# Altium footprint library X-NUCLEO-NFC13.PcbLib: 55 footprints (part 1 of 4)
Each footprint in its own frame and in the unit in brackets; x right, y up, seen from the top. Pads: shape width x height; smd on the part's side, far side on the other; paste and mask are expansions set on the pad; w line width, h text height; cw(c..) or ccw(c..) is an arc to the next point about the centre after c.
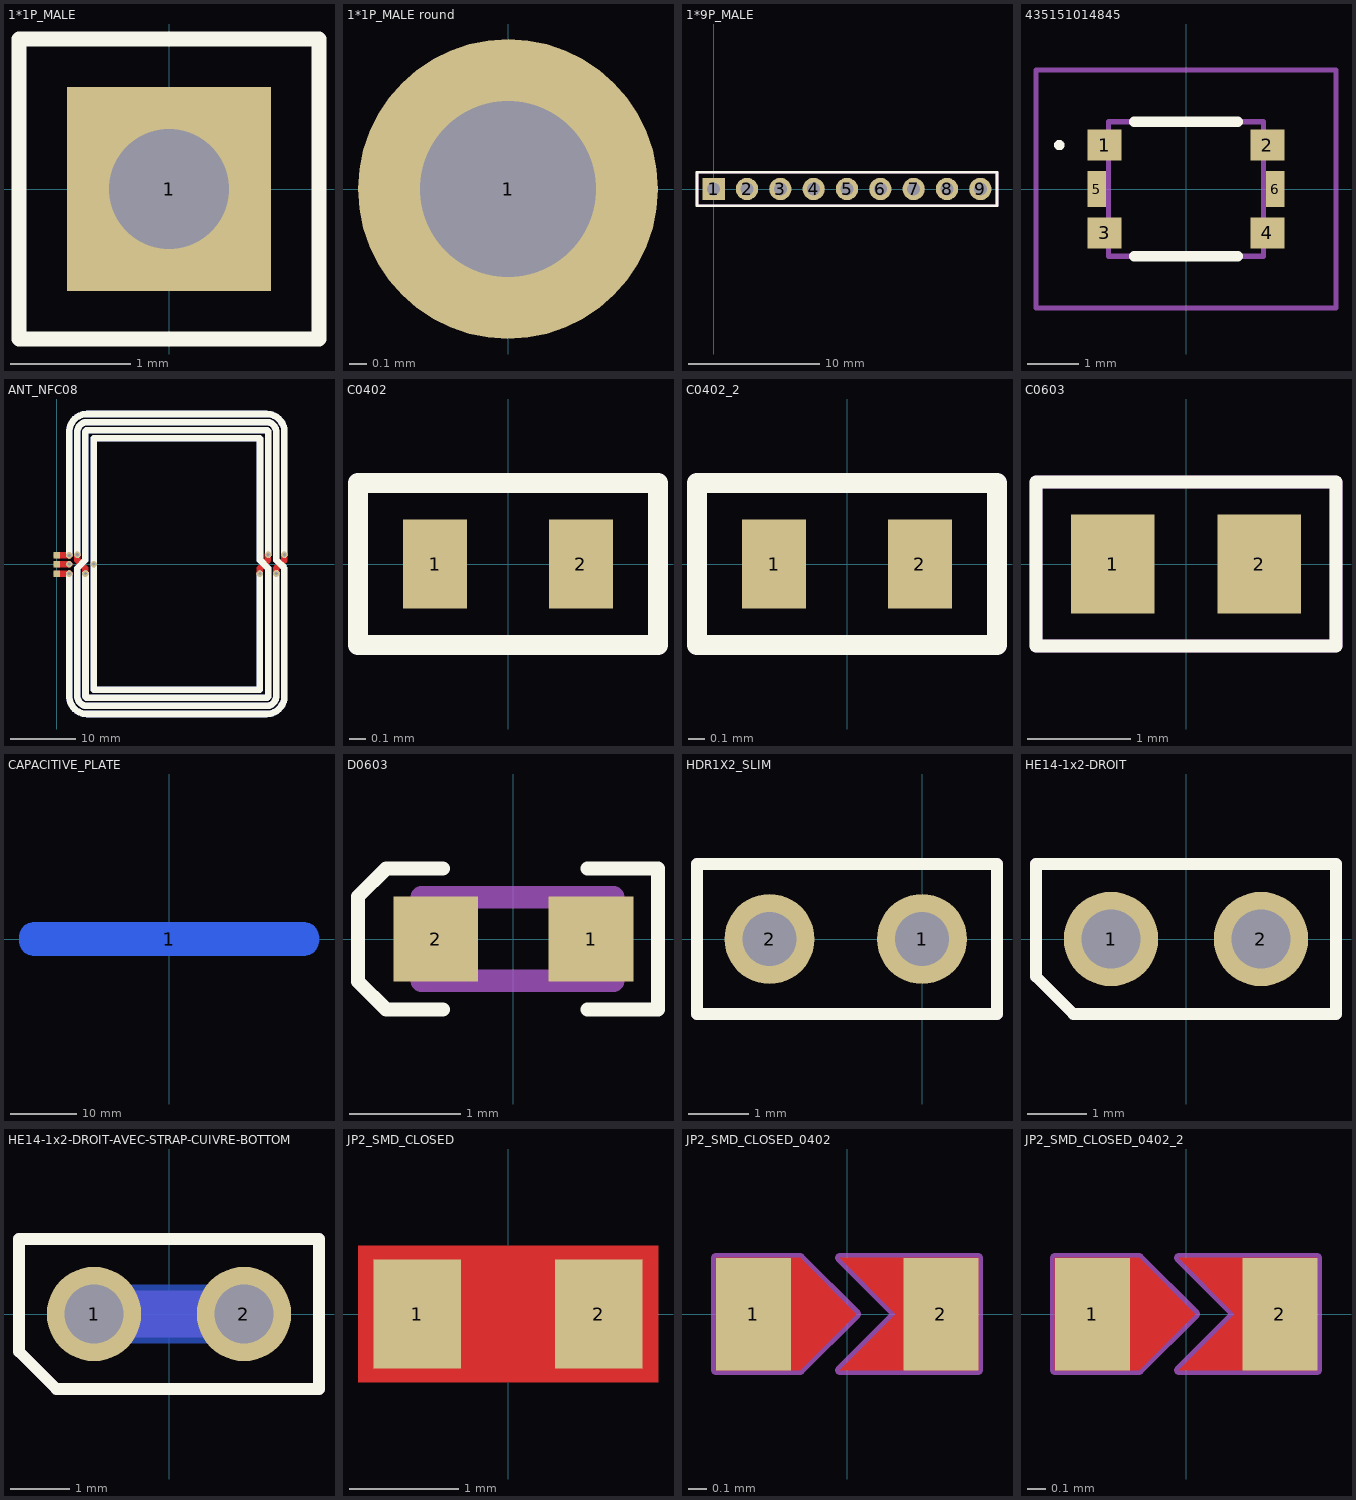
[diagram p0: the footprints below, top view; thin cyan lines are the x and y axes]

## 1*1P_MALE [mm]
height 6
pads (1):
  rect 1.7x1.7 hole 1 mask+0.05: 1(0,0)
Top Overlay:
  lines w0.127: -1.25,-1.25 1.25,-1.25 ; -1.25,-1.25 -1.25,1.25 ; -1.25,-1.25 -1.25,1.25 ; -1.25,-1.25 1.25,-1.25 ; -1.25,1.25 1.25,1.25 ; -1.25,1.25 1.25,1.25 ; 1.25,-1.25 1.25,1.25 ; 1.25,-1.25 1.25,1.25
Top Assembly:
  text ".Designator" at -1.24,1.521 h0.8

## 1*1P_MALE round [mm]
height 6
pads (1):
  round 1.7 hole 1: 1(0,0)

## 1*9P_MALE [mm]
height 6
pads (9):
  rect 1.7x1.7 hole 1: 1(0,0)
  round 1.7 hole 1: 2(2.54,0) 3(5.08,0) 4(7.62,0) 5(10.16,0) 6(12.7,0) 7(15.24,0) 8(17.78,0) 9(20.32,0)
Top Overlay:
  lines w0.2: 21.59,1.265 21.59,-1.27 -1.27,-1.27 -1.27,1.27 21.59,1.27
Top Assembly:
  lines w0.2: 21.59,1.265 21.59,-1.27 -1.27,-1.27 -1.27,1.27 21.59,1.27
  text ".Designator" at 6.26,1.521 h0.8
  text "1" at -0.25,-0.5 h0.8

## 435151014845 [mm]
pads (6):
  rect 0.65x0.6 smd: 1(-1.575,0.85) 2(1.575,0.85) 3(-1.575,-0.85) 4(1.575,-0.85)
  rect 0.35x0.7 smd: 5(-1.725,0) 6(1.725,0)
Top Overlay:
  lines w0.1: -2.5,0.85 ccw(c-2.45,0.85) -2.4,0.85 ccw(c-2.45,0.85) -2.5,0.85
  lines w0.2: -1,-1.3 1,-1.3 ; -1,1.3 1,1.3
Top Assembly:
  lines w0.1: -1.5,-1.3 -1.5,1.3 1.5,1.3 1.5,-1.3 -1.5,-1.3
Mechanical 20:
  lines w0.1: -2.9,-2.3 -2.9,2.3 2.9,2.3 2.9,-2.3 -2.9,-2.3
3D body "435151014845.stp": height 1.36, standoff -0.05, extent -1.765,-1.295 1.735,1.305

## ANT_NFC08 [mm] "40mm times 35mm"
pads (3):
  rect 1x1 smd paste-10: 1(0,1.325) 2(0,-1.45) 3(0,0)
via 34.9,1.45 diameter 1 hole 0.5
via 33.659,-1.441 diameter 1 hole 0.5
via 31.138,-1.445 diameter 1 hole 0.5
via 32.379,1.445 diameter 1 hole 0.5
via 3.138,1.445 diameter 1 hole 0.5
via 4.379,-1.445 diameter 1 hole 0.5
via 1.9,0 diameter 1 hole 0.5
via 5.641,0 diameter 1 hole 0.5
via 1.891,-1.45 diameter 1 hole 0.5
via 1.891,1.325 diameter 1 hole 0.5
Top Layer:
  lines w1: 0,-1.45 1.891,-1.45 ; 0,0 1.9,0 ; 0,1.325 1.891,1.325 ; 3.129,1.436 3.129,0.62 4.37,-0.621 4.37,-1.436 ; 31.129,-1.436 31.129,-0.62 32.37,0.621 32.37,1.436 ; 33.65,-1.432 33.65,-0.616 34.891,0.625 34.891,1.441
Mid-Layer 1:
  lines w1: 1.9,0 5.641,0
Bottom Layer:
  lines w1: 1.891,-1.45 1.891,-20.234 ccw(c4.641,-20.234) 4.641,-22.984 32.141,-22.984 ; 1.891,1.325 1.891,20.266 cw(c4.641,20.266) 4.641,23.016 32.141,23.016 ; 3.129,-0.62 4.37,0.621 4.37,0.63 4.37,20.246 ; 3.141,-0.62 3.141,-20.234 ccw(c4.641,-20.234) 4.641,-21.734 32.141,-21.734 ; 3.141,1.448 3.141,20.266 cw(c4.641,20.266) 4.641,21.766 32.141,21.766 ; 4.391,-1.457 4.391,-20.234 ccw(c4.641,-20.234) 4.641,-20.484 32.257,-20.484 32.391,-20.35 32.391,-0.621 ; 4.391,20.266 cw(c4.641,20.266) 4.641,20.516 32.141,20.516 cw(c32.141,20.266) 32.391,20.266 ; 31.129,0.62 32.37,-0.621 32.37,-0.63 ; 31.141,-1.445 31.141,-19.234 5.641,-19.234 5.641,19.266 31.141,19.266 ; 31.15,0.62 31.15,19.257 ; 32.141,-20.484 ccw(c32.141,-20.234) 32.391,-20.234 ; 32.382,1.445 32.382,20.266 ; 33.641,-20.234 cw(c32.141,-20.234) 32.141,-21.734 ; 33.641,0.625 33.641,20.266 ccw(c32.141,20.266) 32.141,21.766 ; 33.65,0.625 34.891,-0.616 34.891,-0.625 34.891,-20.234 cw(c32.141,-20.234) 32.141,-22.984 ; 33.659,-20.216 33.659,-1.441 ; 34.891,1.45 34.891,20.266 ccw(c32.141,20.266) 32.141,23.016 ; 32.141,-22.984 32.141,-22.984 ; 32.141,-22.984 32.141,-22.984 ; 32.141,-22.984 32.141,-22.984 ; 32.141,-22.984 32.141,-22.984 ; 32.141,-22.984 32.141,-22.984 ; 32.141,-22.984 32.141,-22.984 ; 32.141,-22.984 32.141,-22.984 ; 32.141,-22.984 32.141,-22.984 ; 32.141,-22.984 32.141,-22.984 ; 32.141,-22.984 32.141,-22.984 ; 32.141,-22.984 32.141,-22.984 ; 32.141,-22.984 32.141,-22.984 ; 32.141,-22.984 32.141,-22.984 ; 32.141,-22.984 32.141,-22.984 ; 32.141,-22.984 32.141,-22.984 ; 32.141,-22.984 32.141,-22.984 ; 32.141,-22.984 32.141,-22.984 ; 32.141,-22.984 32.141,-22.984 ; 32.141,-22.984 32.141,-22.984 ; 32.141,-22.984 32.141,-22.984 ; 32.141,-22.984 32.141,-22.984 ; 32.141,-22.984 32.141,-22.984 ; 32.141,-22.984 32.141,-22.984 ; 32.141,-22.984 32.141,-22.984 ; 32.141,-22.984 32.141,-22.984 ; 32.141,-22.984 32.141,-22.984 ; 32.141,-22.984 32.141,-22.984 ; 32.141,-22.984 32.141,-22.984 ; 32.141,-22.984 32.141,-22.984 ; 32.141,-22.984 32.141,-22.984 ; 32.141,-22.984 32.141,-22.984 ; 32.141,-22.984 32.141,-22.984 ; 32.141,-22.984 32.141,-22.984 ; 32.141,-22.984 32.141,-22.984 ; 32.141,-22.984 32.141,-22.984 ; 32.141,-22.984 32.141,-22.984 ; 32.141,-22.984 32.141,-22.984 ; 32.141,-22.984 32.141,-22.984 ; 32.141,-22.984 32.141,-22.984 ; 32.141,-22.984 32.141,-22.984 ; 32.141,-22.984 32.141,-22.984 ; 32.141,-22.984 32.141,-22.984 ; 32.141,-22.984 32.141,-22.984 ; 32.141,-22.984 32.141,-22.984 ; 32.141,-22.984 32.141,-22.984 ; 32.141,-22.984 32.141,-22.984 ; 32.141,-22.984 32.141,-22.984 ; 32.141,-22.984 32.141,-22.984 ; 32.141,-22.984 32.141,-22.984 ; 32.141,-21.734 32.141,-21.734 ; 32.141,-21.734 32.141,-21.734 ; 32.141,-21.734 32.141,-21.734 ; 32.141,-21.734 32.141,-21.734 ; 32.141,-21.734 32.141,-21.734 ; 32.141,-21.734 32.141,-21.734 ; 32.141,-21.734 32.141,-21.734 ; 32.141,-21.734 32.141,-21.734 ; 32.141,-21.734 32.141,-21.734 ; 32.141,-21.734 32.141,-21.734 ; 32.141,-21.734 32.141,-21.734 ; 32.141,-21.734 32.141,-21.734 ; 32.141,-21.734 32.141,-21.734 ; 32.141,-21.734 32.141,-21.734 ; 32.141,-21.734 32.141,-21.734 ; 32.141,-21.734 32.141,-21.734 ; 32.141,-21.734 32.141,-21.734 ; 32.141,-21.734 32.141,-21.734 ; 32.141,-21.734 32.141,-21.734 ; 32.141,-21.734 32.141,-21.734 ; 32.141,-21.734 32.141,-21.734 ; 32.141,-21.734 32.141,-21.734 ; 32.141,-21.734 32.141,-21.734 ; 32.141,-21.734 32.141,-21.734 ; 32.141,-21.734 32.141,-21.734 ; 32.141,-21.734 32.141,-21.734 ; 32.141,-21.734 32.141,-21.734 ; 32.141,-21.734 32.141,-21.734 ; 32.141,-21.734 32.141,-21.734 ; 32.141,-21.734 32.141,-21.734 ; 32.141,-21.734 32.141,-21.734 ; 32.141,-21.734 32.141,-21.734 ; 32.141,-21.734 32.141,-21.734 ; 32.141,-21.734 32.141,-21.734 ; 32.141,-21.734 32.141,-21.734 ; 32.141,-21.734 32.141,-21.734 ; 32.141,-21.734 32.141,-21.734 ; 32.141,-21.734 32.141,-21.734 ; 32.141,-21.734 32.141,-21.734 ; 32.141,-21.734 32.141,-21.734 ; 32.141,-21.734 32.141,-21.734 ; 32.141,-21.734 32.141,-21.734 ; 32.141,-21.734 32.141,-21.734 ; 32.141,-21.734 32.141,-21.734 ; 32.141,-21.734 32.141,-21.734 ; 32.141,-21.734 32.141,-21.734 ; 32.141,-21.734 32.141,-21.734 ; 32.141,-21.734 32.141,-21.734 ; 32.141,-21.734 32.141,-21.734 ; 32.141,21.766 32.141,21.766 ; 32.141,21.766 32.141,21.766 ; 32.141,21.766 32.141,21.766 ; 32.141,21.766 32.141,21.766 ; 32.141,21.766 32.141,21.766 ; 32.141,21.766 32.141,21.766 ; 32.141,21.766 32.141,21.766 ; 32.141,21.766 32.141,21.766 ; 32.141,21.766 32.141,21.766 ; 32.141,21.766 32.141,21.766 ; 32.141,21.766 32.141,21.766 ; 32.141,21.766 32.141,21.766 ; 32.141,21.766 32.141,21.766 ; 32.141,21.766 32.141,21.766 ; 32.141,21.766 32.141,21.766 ; 32.141,21.766 32.141,21.766 ; 32.141,21.766 32.141,21.766 ; 32.141,21.766 32.141,21.766 ; 32.141,21.766 32.141,21.766 ; 32.141,21.766 32.141,21.766 ; 32.141,21.766 32.141,21.766 ; 32.141,21.766 32.141,21.766 ; 32.141,21.766 32.141,21.766 ; 32.141,21.766 32.141,21.766 ; 32.141,21.766 32.141,21.766 ; 32.141,21.766 32.141,21.766 ; 32.141,21.766 32.141,21.766 ; 32.141,21.766 32.141,21.766 ; 32.141,21.766 32.141,21.766 ; 32.141,21.766 32.141,21.766 ; 32.141,21.766 32.141,21.766 ; 32.141,21.766 32.141,21.766 ; 32.141,21.766 32.141,21.766 ; 32.141,21.766 32.141,21.766 ; 32.141,21.766 32.141,21.766 ; 32.141,23.016 32.141,23.016 ; 32.141,23.016 32.141,23.016 ; 32.141,23.016 32.141,23.016 ; 32.141,23.016 32.141,23.016 ; 32.141,23.016 32.141,23.016 ; 32.141,23.016 32.141,23.016 ; 32.141,23.016 32.141,23.016 ; 32.141,23.016 32.141,23.016 ; 32.141,23.016 32.141,23.016 ; 32.141,23.016 32.141,23.016 ; 32.141,23.016 32.141,23.016 ; 32.141,23.016 32.141,23.016 ; 32.141,23.016 32.141,23.016 ; 32.141,23.016 32.141,23.016 ; 32.141,23.016 32.141,23.016 ; 32.141,23.016 32.141,23.016 ; 32.141,23.016 32.141,23.016 ; 32.141,23.016 32.141,23.016 ; 32.141,23.016 32.141,23.016 ; 32.141,23.016 32.141,23.016 ; 32.141,23.016 32.141,23.016 ; 32.141,23.016 32.141,23.016 ; 32.141,23.016 32.141,23.016 ; 32.141,23.016 32.141,23.016 ; 32.141,23.016 32.141,23.016 ; 32.141,23.016 32.141,23.016 ; 32.141,23.016 32.141,23.016 ; 32.141,23.016 32.141,23.016 ; 32.141,23.016 32.141,23.016 ; 32.141,23.016 32.141,23.016 ; 32.141,23.016 32.141,23.016 ; 32.141,23.016 32.141,23.016 ; 32.141,23.016 32.141,23.016 ; 32.141,23.016 32.141,23.016 ; 32.141,23.016 32.141,23.016
Top Overlay:
  drawing of 210 lines, arcs and shapes, not listed

## C0402 [mil]
pads (2):
  rect 15.75x22 smd paste+0 mask+0: 1(-18,0) 2(18,0)
Top Overlay:
  lines w5: -37,-20 37,-20 37,20 -37,20 -37,-20
Top Assembly:
  lines w5: -37,-20 37,-20 37,20 -37,20 -37,-20
  text ".Designator" at -39.37,29.53 h23.62
3D body: height 11.81, standoff 0, extent -26,-11 -22,11
3D body: height 11.81, standoff 0, extent 22,-11 26,11
3D body: height 11.81, standoff 0, extent -22,-11 22,11

## C0402_2 [mil]
pads (2):
  rect 15.75x22 smd paste+0 mask+0: 1(-18,0) 2(18,0)
Top Overlay:
  lines w5: -37,-20 37,-20 37,20 -37,20 -37,-20
Top Assembly:
  lines w5: -37,-20 37,-20 37,20 -37,20 -37,-20
  text ".Designator" at -49.21,29.53 h23.62
3D body: height 11.81, standoff 0, extent -26,-11 -22,11
3D body: height 11.81, standoff 0, extent 22,-11 26,11
3D body: height 11.81, standoff 0, extent -22,-11 22,11

## C0603 [mil]
pads (2):
  rect 32x38 smd paste+0 mask+0: 1(-28,0) 2(28,0)
Top Overlay:
  lines w5: -57.5,-31.5 57.5,-31.5 57.5,31.5 -57.5,31.5 -57.5,-31.5
Top Assembly:
  lines w5: -57.5,-31.5 57.5,-31.5 57.5,31.5 -57.5,31.5 -57.5,-31.5
  text ".Designator" at -59.06,39.37 h23.62
3D body: height 20, standoff 0, extent -30.56,-18.95 32.43,19.05
3D body: height 20, standoff 0, extent 32.43,-18.95 40.31,19.05
3D body: height 20, standoff 0, extent -38.43,-18.95 -30.56,19.05

## CAPACITIVE_PLATE [mm]
pads (1):
  rrect90% 45x5 smd far side mask+0.102: 1(0,0)

## D0603 [mil]
pads (2):
  rect 30x30 smd mask+1.97: 1(27.5,0) 2(-27.5,0)
Top Overlay:
  lines w5: -25,-25 -45,-25 -55,-15 -55,15 -45,25 -25,25 ; 26.18,-25 51.18,-25 51.18,25 26.18,25
Top Assembly:
  lines w7.87: -19.68,-11.81 -19.68,11.81 ; -32.48,-14.76 -32.48,14.76 35.43,14.76 35.43,-14.76 -32.48,-14.76
  text ".Designator" at -45,25 h23.62
3D body: height 11.81, standoff 0, extent -32.48,-14.76 35.43,14.76
3D body: height 21.65, standoff 1.97, extent -9.84,-9.69 9.85,9.7

## HDR1X2_SLIM [mm] "Connector; Header; 2 Position"
pads (2):
  round 1.5 hole 0.9: 1(0,0) 2(-2.54,0)
Top Overlay:
  lines w0.2: -3.75,-1.25 -3.75,1.25 1.25,1.25 1.25,-1.25 -3.75,-1.25
Top Assembly:
  lines w0.2: -3.75,-1.25 -3.75,1.25 1.25,1.25 1.25,-1.25 -3.75,-1.25
  text ".Designator" at -3.756,1.614 h0.6

## HE14-1x2-DROIT [mm]
pads (2):
  round 1.6 hole 1: 1(-1.27,0) 2(1.27,0)
Top Overlay:
  lines w0.2: -2.54,-0.635 -1.905,-1.27 2.54,-1.27 2.54,1.27 -2.54,1.27 -2.54,-0.635
Top Assembly:
  lines w0.2: -2.54,-0.635 -1.905,-1.27 2.54,-1.27 2.54,1.27 -2.54,1.27 -2.54,-0.635
  text "1" at -1.5,-0.5 h1.05
  text ".Designator" at -6.825,-0.87 h1.05
3D body "TSW-102-23-G-S.stp": height 8.38, standoff -2.92, extent -2.667,-1.27 2.54,1.27

## HE14-1x2-DROIT-AVEC-STRAP-CUIVRE-BOTTOM [mm]
pads (2):
  round 1.6 hole 1: 1(-1.27,0) 2(1.27,0)
Bottom Layer:
  lines w1: -1.27,0 1.27,0
Top Overlay:
  lines w0.2: -2.54,-0.635 -2.54,1.27 2.54,1.27 2.54,-1.27 -1.905,-1.27 -2.54,-0.635
Top Assembly:
  lines w0.2: -2.54,-0.635 -2.54,1.27 2.54,1.27 2.54,-1.27 -1.905,-1.27 -2.54,-0.635
  lines w0.8: -1.27,0 1.27,0
  text ".Designator" at -1.78,-3.05 h1.05
  text "1" at -1.5,-0.5 h1.05
3D body "TSW-102-23-G-S.stp": height 8.38, standoff -2.92, extent -2.667,-1.27 2.54,1.27

## JP2_SMD_CLOSED [mm]
height 2
pads (2):
  rect 0.8x1 smd: 1(-0.832,0) 2(0.832,0)
Top Layer:
  pour cut-out: 1.375,0.625 1.375,-0.625 -1.375,-0.625 -1.375,0.625
  region: -0.087,0.5 0.413,0 -0.087,-0.5 0.832,-0.5 0.832,0.5
  region: -0.832,-0.5 -0.832,0.5 -0.348,0.5 0.152,0 -0.348,-0.5
Top Paste:
  rectangle: -1.225,-0.5 1.225,0.5
Top Solder:
  rectangle: -1.372,-0.61 1.372,0.61
Top Assembly:
  lines w0.05: -0.832,-0.5 -0.832,0.5 -0.348,0.5 0.152,0 -0.348,-0.5 -0.832,-0.5 ; -0.087,-0.5 0.413,0 -0.087,0.5 0.832,0.5 0.832,-0.5 -0.087,-0.5
  text ".Designator" at -1.506,0.614 h0.6
3D body: height 0.3, standoff 0, extent -1.15,-0.375 1.1,0.375

## JP2_SMD_CLOSED_0402 [mm]
height 2
pads (2):
  rect 0.4x0.6 smd mask+0.05: 1(-0.5,0) 2(0.5,0)
Top Layer:
  region: -0.7,-0.3 -0.7,0.3 -0.25,0.3 0.05,0 -0.25,-0.3
  region: -0.04,0.3 0.26,0 -0.04,-0.3 0.7,-0.3 0.7,0.3
Top Paste:
  rectangle: -0.7,-0.3 0.7,0.3
Top Solder:
  rectangle: -0.75,-0.35 0.75,0.35
Top Assembly:
  lines w0.05: -0.7,-0.3 -0.7,0.3 -0.25,0.3 0.05,0 -0.25,-0.3 -0.7,-0.3 ; -0.04,-0.3 0.26,0 -0.04,0.3 0.7,0.3 0.7,-0.3 -0.04,-0.3
  text ".Designator" at -1.363,0.563 h0.6
3D body: height 0.2, standoff 0, extent -0.55,-0.225 0.575,0.225

## JP2_SMD_CLOSED_0402_2 [mm]
pads (2):
  rect 0.4x0.6 smd mask+0.05: 1(-0.5,0) 2(0.5,0)
Top Layer:
  region: -0.04,0.3 0.26,0 -0.04,-0.3 0.7,-0.3 0.7,0.3
  region: -0.7,-0.3 -0.7,0.3 -0.25,0.3 0.05,0 -0.25,-0.3
Top Paste:
  rectangle: -0.7,-0.3 0.7,0.3
Top Solder:
  rectangle: -0.75,-0.35 0.75,0.35
Top Assembly:
  lines w0.05: -0.7,-0.3 -0.25,-0.3 0.05,0 -0.25,0.3 -0.7,0.3 -0.7,-0.3 ; -0.04,-0.3 0.7,-0.3 0.7,0.3 -0.04,0.3 0.26,0 -0.04,-0.3
  text ".Designator" at -1.363,0.563 h0.6
3D body: height 0.2, standoff 0, extent -0.55,-0.225 0.575,0.225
